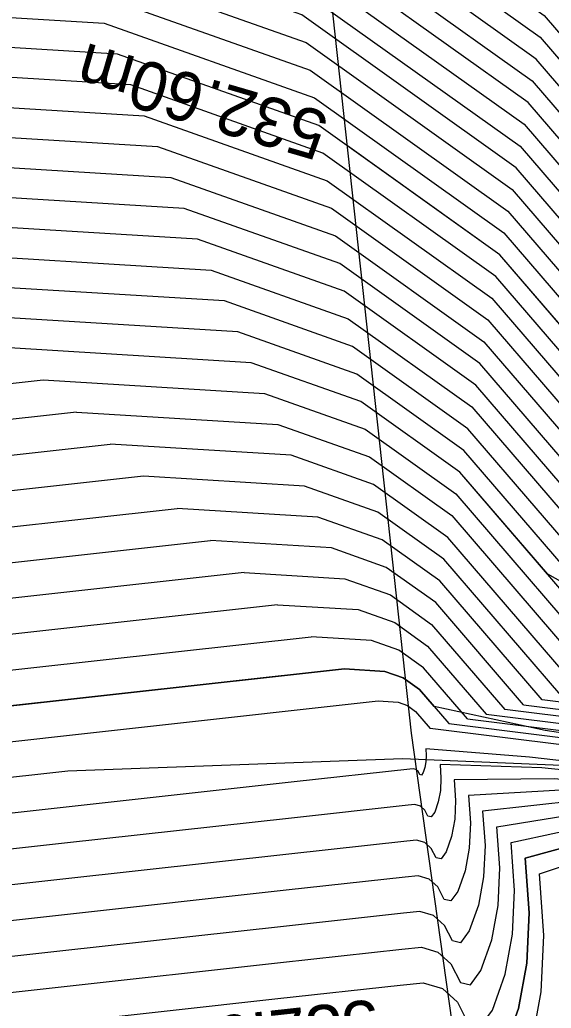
# Model space of a CAD drawing. Extents: x -866683 to -866410, y -1041951 to -1040252.
# Drawn here: x -866458.01 to -866454.76, y -1041924.15 to -1041918.11 of the extents above; entities that cross this region are included whole.
import ezdxf

# ---------------------------------------------------------------- set-up
doc = ezdxf.new("R2010")
doc.units = 0
for name, color, linetype in [('BODY', 7, 'Continuous'), ('BODY_2016', 7, 'Continuous'), ('BREAKLINE', 7, 'Continuous'), ('V-VEDL', 7, 'Continuous'), ('V_po_cm', 7, 'Continuous')]:
    doc.layers.add(name, color=color, linetype=linetype)

msp = doc.modelspace()

# ---------------------------------------------------------------- linework, layer by layer
at = {"layer": 'BREAKLINE'}
msp.add_lwpolyline([(-866451.679, -1041950.508), (-866455.618, -1041922.473), (-866456.719, -1041912.396), (-866455.207, -1041909.853), (-866453.752, -1041908.342), (-866450, -1041907.538), (-866447.7, -1041908.076), (-866445.165, -1041909.459), (-866437.422, -1041915.176), (-866426.565, -1041925.108), (-866438.22, -1041915.868), (-866445.312, -1041910.554), (-866447.7, -1041908.076)], dxfattribs=at)
at = {"layer": 'V-VEDL'}
for points in [[(-866462.1678, -1041916.1944), (-866458.2322, -1041916.4356), (-866456.4431, -1041917.0707), (-866454.8326, -1041918.2202), (-866453.4008, -1041919.8842), (-866452.2221, -1041921.0215), (-866451.2966, -1041921.6321), (-866449.952, -1041921.7999)], [(-866449.9128, -1041922.2361), (-866452.0438, -1041921.9702), (-866453.0823, -1041921.5002), (-866454.0937, -1041920.6932), (-866455.0781, -1041919.5492), (-866456.1853, -1041918.7589), (-866457.4153, -1041918.3223), (-866460.121, -1041918.1565)], [(-866449.8737, -1041922.6724), (-866452.791, -1041922.3082), (-866453.9424, -1041921.9789), (-866454.7865, -1041921.5022), (-866455.3235, -1041920.8782), (-866455.9274, -1041920.4471), (-866456.5983, -1041920.209), (-866458.0742, -1041920.1185)], [(-866462.3233, -1041923.0423), (-866462.0929, -1041922.841), (-866461.3549, -1041922.7006), (-866459.9943, -1041922.5205), (-866456.0274, -1041922.0806)], [(-866449.8345, -1041923.1086), (-866453.5381, -1041922.6463), (-866454.8025, -1041922.4576), (-866455.4794, -1041922.3112), (-866455.5689, -1041922.2072), (-866455.6696, -1041922.1354), (-866455.7814, -1041922.0957), (-866456.0274, -1041922.0806)], [(-866455.8588, -1041924.2509), (-866455.5364, -1041924.2176), (-866455.403, -1041924.2573), (-866455.2974, -1041924.3533), (-866455.2196, -1041924.5057), (-866455.1383, -1041924.5239), (-866455.0534, -1041924.4077), (-866454.9651, -1041924.1572), (-866454.9139, -1041923.8786), (-866454.9, -1041923.5718), (-866454.9234, -1041923.2368), (-866454.3666, -1041923.0849), (-866453.2296, -1041923.1162), (-866449.7953, -1041923.5448)]]:
    msp.add_lwpolyline(points, dxfattribs=at)
at = {"layer": 'V_po_cm'}
for points in [[(-866462.3725, -1041915.9982), (-866458.3139, -1041916.247), (-866456.4689, -1041916.9019), (-866454.8081, -1041918.0873), (-866451.8549, -1041921.5193)], [(-866452.083, -1041921.5771), (-866454.8572, -1041918.3531), (-866456.4173, -1041917.2395), (-866458.1505, -1041916.6243), (-866461.9631, -1041916.3906)], [(-866457.9843, -1041916.5236), (-866456.4431, -1041917.0707), (-866454.8326, -1041918.2202), (-866454.4544, -1041918.6598)], [(-866461.7584, -1041916.5869), (-866458.0689, -1041916.813), (-866456.3915, -1041917.4083), (-866454.8817, -1041918.486), (-866452.197, -1041921.606)], [(-866452.3111, -1041921.6349), (-866454.9063, -1041918.6189), (-866456.3658, -1041917.5772), (-866457.9872, -1041917.0016), (-866461.5538, -1041916.7831)], [(-866461.3491, -1041916.9793), (-866457.9055, -1041917.1903), (-866456.34, -1041917.746), (-866454.9308, -1041918.7518), (-866452.4251, -1041921.6638)], [(-866461.1444, -1041917.1755), (-866457.8238, -1041917.379), (-866456.3142, -1041917.9148), (-866454.9553, -1041918.8847), (-866452.5391, -1041921.6927)], [(-866452.6532, -1041921.7216), (-866454.9799, -1041919.0176), (-866456.2884, -1041918.0836), (-866457.7421, -1041917.5676), (-866460.9397, -1041917.3717)], [(-866460.735, -1041917.5679), (-866457.6604, -1041917.7563), (-866456.2626, -1041918.2524), (-866455.0044, -1041919.1505), (-866452.7672, -1041921.7505)], [(-866460.5304, -1041917.7641), (-866457.5787, -1041917.945), (-866456.2368, -1041918.4213), (-866455.029, -1041919.2834), (-866452.8812, -1041921.7794)], [(-866460.3257, -1041917.9603), (-866457.497, -1041918.1336), (-866456.211, -1041918.5901), (-866455.0535, -1041919.4163), (-866452.9953, -1041921.8083)], [(-866453.2233, -1041921.8661), (-866455.1026, -1041919.6821), (-866456.1595, -1041918.9277), (-866457.3336, -1041918.511), (-866459.9163, -1041918.3527)], [(-866459.7116, -1041918.5489), (-866457.2519, -1041918.6996), (-866456.1337, -1041919.0966), (-866455.1271, -1041919.815), (-866453.3373, -1041921.895)], [(-866459.5069, -1041918.7451), (-866457.1702, -1041918.8883), (-866456.1079, -1041919.2654), (-866455.1517, -1041919.9479), (-866453.4514, -1041921.9239)], [(-866453.1093, -1041921.8372), (-866455.0781, -1041919.5492), (-866456.0239, -1041918.8741)], [(-866459.3023, -1041918.9413), (-866457.0885, -1041919.077), (-866456.0821, -1041919.4342), (-866455.1762, -1041920.0808), (-866453.5654, -1041921.9528)], [(-866453.6794, -1041921.9817), (-866455.2008, -1041920.2137), (-866456.0563, -1041919.603), (-866457.0068, -1041919.2656), (-866459.0976, -1041919.1375)], [(-866453.7935, -1041922.0106), (-866455.2253, -1041920.3466), (-866456.0306, -1041919.7718), (-866456.9251, -1041919.4543), (-866458.8929, -1041919.3337)], [(-866458.6882, -1041919.5299), (-866456.8434, -1041919.643), (-866456.0048, -1041919.9407), (-866455.2499, -1041920.4795), (-866453.9075, -1041922.0395)], [(-866454.0215, -1041922.0684), (-866455.2744, -1041920.6124), (-866455.979, -1041920.1095), (-866456.7617, -1041919.8317), (-866458.4835, -1041919.7261)], [(-866454.1356, -1041922.0973), (-866455.2989, -1041920.7453), (-866455.9532, -1041920.2783), (-866456.68, -1041920.0203), (-866458.2789, -1041919.9223)], [(-866454.2496, -1041922.1262), (-866455.3235, -1041920.8782), (-866455.9274, -1041920.4471), (-866456.5983, -1041920.209), (-866458.0742, -1041920.1185)], [(-866462.5037, -1041921.0226), (-866462.3342, -1041920.8745), (-866461.791, -1041920.7711), (-866460.7894, -1041920.6385), (-866457.8695, -1041920.3147)], [(-866457.8695, -1041920.3147), (-866456.5166, -1041920.3977), (-866455.9016, -1041920.616), (-866455.348, -1041921.0111), (-866454.3636, -1041922.1551)], [(-866457.6648, -1041920.511), (-866460.7011, -1041920.8476), (-866461.7425, -1041920.9855), (-866462.3073, -1041921.093), (-866462.4837, -1041921.247)], [(-866457.6648, -1041920.511), (-866456.435, -1041920.5863), (-866455.8758, -1041920.7848), (-866455.3726, -1041921.144), (-866454.4777, -1041922.184)], [(-866462.4636, -1041921.4714), (-866462.2805, -1041921.3115), (-866461.6941, -1041921.1999), (-866460.6127, -1041921.0567), (-866457.4601, -1041920.7072)], [(-866454.5917, -1041922.2129), (-866455.3971, -1041921.2769), (-866455.8501, -1041920.9536), (-866456.3533, -1041920.775), (-866457.4601, -1041920.7072)], [(-866457.2555, -1041920.9034), (-866460.5244, -1041921.2658), (-866461.6456, -1041921.4143), (-866462.2537, -1041921.53), (-866462.4436, -1041921.6958)], [(-866454.7057, -1041922.2418), (-866455.4217, -1041921.4098), (-866455.8243, -1041921.1224), (-866456.2716, -1041920.9637), (-866457.2555, -1041920.9034)], [(-866462.4235, -1041921.9203), (-866462.2269, -1041921.7485), (-866461.5972, -1041921.6287), (-866460.436, -1041921.475), (-866457.0508, -1041921.0996)], [(-866454.8198, -1041922.2707), (-866455.4462, -1041921.5427), (-866455.7985, -1041921.2912), (-866456.1899, -1041921.1523), (-866457.0508, -1041921.0996)], [(-866462.4035, -1041922.1447), (-866462.2001, -1041921.967), (-866461.5487, -1041921.8431), (-866460.3477, -1041921.6841), (-866456.8461, -1041921.2958)], [(-866454.9338, -1041922.2996), (-866455.4707, -1041921.6756), (-866455.7727, -1041921.4601), (-866456.1082, -1041921.341), (-866456.8461, -1041921.2958)], [(-866456.6414, -1041921.492), (-866460.2593, -1041921.8932), (-866461.5003, -1041922.0575), (-866462.1733, -1041922.1855), (-866462.3834, -1041922.3691)], [(-866456.6414, -1041921.492), (-866456.0265, -1041921.5297), (-866455.7469, -1041921.6289), (-866455.4953, -1041921.8085), (-866455.0478, -1041922.3285)], [(-866456.4367, -1041921.6882), (-866460.171, -1041922.1023), (-866461.4518, -1041922.2719), (-866462.1465, -1041922.404), (-866462.3634, -1041922.5935)], [(-866456.4367, -1041921.6882), (-866455.9448, -1041921.7183), (-866455.7211, -1041921.7977), (-866455.5198, -1041921.9414), (-866455.1619, -1041922.3574)], [(-866462.3433, -1041922.8179), (-866462.1197, -1041922.6225), (-866461.4034, -1041922.4863), (-866460.0826, -1041922.3114), (-866456.232, -1041921.8844)], [(-866455.2759, -1041922.3863), (-866455.5444, -1041922.0743), (-866455.6954, -1041921.9665), (-866455.8631, -1041921.907), (-866456.232, -1041921.8844)], [(-866456.0274, -1041922.0806), (-866458.2347, -1041922.3254)], [(-866456.0274, -1041922.0806), (-866455.7814, -1041922.0957), (-866455.6696, -1041922.1354), (-866455.5689, -1041922.2072), (-866455.3899, -1041922.4152)], [(-866462.3032, -1041923.2667), (-866462.0661, -1041923.0595), (-866461.3065, -1041922.915), (-866459.9059, -1041922.7296), (-866455.8227, -1041922.2768)], [(-866455.8227, -1041922.2768), (-866455.6997, -1041922.2843), (-866455.6438, -1041922.3042), (-866455.5935, -1041922.3401), (-866455.504, -1041922.4441)], [(-866447.6566, -1041942.39), (-866443.865, -1041936.08), (-866442.6338, -1041933.8151), (-866442.0673, -1041932.4403), (-866442.1655, -1041931.9556), (-866442.1705, -1041931.1056), (-866442.0824, -1041929.8904), (-866441.9012, -1041928.3099), (-866442.5034, -1041926.7821), (-866443.8893, -1041925.307), (-866446.0587, -1041923.8847), (-866447.6856, -1041922.984), (-866448.77, -1041922.6051), (-866449.3121, -1041922.7478), (-866450.2251, -1041922.774), (-866451.5093, -1041922.6839), (-866454.8198, -1041922.2707)], [(-866447.9552, -1041942.6485), (-866444.0987, -1041936.2305), (-866442.8465, -1041933.9269), (-866442.2703, -1041932.5286), (-866442.3702, -1041932.0356), (-866442.3753, -1041931.1711), (-866442.2857, -1041929.935), (-866442.1013, -1041928.3275), (-866442.6833, -1041926.7936), (-866444.0317, -1041925.3334), (-866446.1464, -1041923.9469), (-866447.7324, -1041923.0689), (-866448.7895, -1041922.6995), (-866449.3179, -1041922.8386), (-866450.2481, -1041922.8592), (-866451.5801, -1041922.7613), (-866455.0478, -1041922.3285)], [(-866454.9338, -1041922.2996), (-866451.5447, -1041922.7226), (-866450.2366, -1041922.8166), (-866449.315, -1041922.7932), (-866448.7798, -1041922.6523), (-866447.709, -1041923.0265), (-866446.1025, -1041923.9158), (-866443.9605, -1041925.3202), (-866442.5934, -1041926.7878), (-866442.0012, -1041928.3187), (-866442.184, -1041929.9127), (-866442.2729, -1041931.1384), (-866442.2678, -1041931.9956), (-866442.1688, -1041932.4844), (-866442.7402, -1041933.871), (-866443.9818, -1041936.1553), (-866447.8059, -1041942.5192)], [(-866455.2759, -1041922.3863), (-866451.6509, -1041922.8387), (-866450.271, -1041922.9444), (-866449.3237, -1041922.9294), (-866448.809, -1041922.7939), (-866447.7791, -1041923.1538), (-866446.2342, -1041924.0091), (-866444.1741, -1041925.3598), (-866442.8632, -1041926.8051), (-866442.3015, -1041928.3451), (-866442.4889, -1041929.9797), (-866442.5801, -1041931.2365), (-866442.5749, -1041932.1155), (-866442.4733, -1041932.6168), (-866443.0592, -1041934.0386), (-866444.3325, -1041936.381), (-866448.2538, -1041942.907)], [(-866455.1619, -1041922.3574), (-866451.6155, -1041922.8), (-866450.2595, -1041922.9018), (-866449.3208, -1041922.884), (-866448.7992, -1041922.7467), (-866447.7558, -1041923.1114), (-866446.1903, -1041923.978), (-866444.1029, -1041925.3466), (-866442.7733, -1041926.7993), (-866442.2014, -1041928.3363), (-866442.3873, -1041929.9573), (-866442.4777, -1041931.2038), (-866442.4725, -1041932.0756), (-866442.3718, -1041932.5727), (-866442.9528, -1041933.9828), (-866444.2156, -1041936.3058), (-866448.1045, -1041942.7777)], [(-866448.5524, -1041943.1654), (-866444.5662, -1041936.5316), (-866443.2719, -1041934.1504), (-866442.6763, -1041932.7051), (-866442.7795, -1041932.1955), (-866442.7848, -1041931.3019), (-866442.6922, -1041930.0243), (-866442.5016, -1041928.3626), (-866443.0431, -1041926.8166), (-866444.3165, -1041925.3861), (-866446.322, -1041924.0713), (-866447.8259, -1041923.2387), (-866448.8285, -1041922.8884), (-866449.3295, -1041923.0203), (-866450.2939, -1041923.0295), (-866451.7217, -1041922.9162), (-866455.504, -1041922.4441)], [(-866455.3899, -1041922.4152), (-866453.1181, -1041922.6987)], [(-866448.8479, -1041922.9828), (-866449.3353, -1041923.1111), (-866450.2949, -1041923.1175), (-866451.7265, -1041923.0018), (-866453.6303, -1041922.7642), (-866454.8985, -1041922.6198), (-866455.5312, -1041922.5685), (-866455.5283, -1041922.6104), (-866455.53, -1041922.6487), (-866455.5364, -1041922.6835), (-866455.5474, -1041922.7148), (-866455.558, -1041922.7294), (-866455.5682, -1041922.7271), (-866455.5779, -1041922.708), (-866455.5911, -1041922.696), (-866455.6078, -1041922.6911), (-866455.6279, -1041922.6932), (-866456.3346, -1041922.7714), (-866457.7278, -1041922.9259), (-866459.8075, -1041923.1565), (-866461.2357, -1041923.3467), (-866462.0125, -1041923.4966), (-866462.2631, -1041923.7155)], [(-866448.7017, -1041943.2947), (-866444.6831, -1041936.6068), (-866443.3782, -1041934.2063), (-866442.7778, -1041932.7492), (-866442.8819, -1041932.2355), (-866442.8872, -1041931.3346), (-866442.7938, -1041930.0466), (-866442.6017, -1041928.3714), (-866443.133, -1041926.8223), (-866444.3877, -1041925.3993), (-866446.3658, -1041924.1024), (-866447.8493, -1041923.2811), (-866448.8382, -1041922.9356), (-866449.3324, -1041923.0657), (-866450.3054, -1041923.0721), (-866451.7571, -1041922.9549), (-866453.6875, -1041922.7139), (-866455.6744, -1041922.6309), (-866457.7178, -1041922.7058), (-866459.8175, -1041922.9387), (-866461.2581, -1041923.1294), (-866462.0393, -1041923.2781), (-866462.2832, -1041923.4911)], [(-866448.8577, -1041923.03), (-866449.3382, -1041923.1565), (-866450.2843, -1041923.1628), (-866451.6959, -1041923.0488), (-866453.5731, -1041922.8145), (-866454.8225, -1041922.6862), (-866455.4443, -1041922.664), (-866455.4385, -1041922.7477), (-866455.442, -1041922.8244), (-866455.4548, -1041922.8941), (-866455.4769, -1041922.9567), (-866455.4981, -1041922.9857), (-866455.5184, -1041922.9812), (-866455.5379, -1041922.9431), (-866455.5643, -1041922.9191), (-866455.5976, -1041922.9091), (-866455.6379, -1041922.9133), (-866456.3513, -1041922.9922), (-866457.7378, -1041923.1459), (-866459.7974, -1041923.3743), (-866461.2133, -1041923.564), (-866461.9857, -1041923.7151), (-866462.2431, -1041923.9399)], [(-866448.8674, -1041923.0772), (-866449.3411, -1041923.2019), (-866450.2738, -1041923.2081), (-866451.6653, -1041923.0957), (-866453.5158, -1041922.8648), (-866454.7465, -1041922.7527), (-866455.3575, -1041922.7594), (-866455.3488, -1041922.8851), (-866455.354, -1041923.0001), (-866455.3731, -1041923.1046), (-866455.4063, -1041923.1985), (-866455.4381, -1041923.2421), (-866455.4686, -1041923.2353), (-866455.4978, -1041923.1781), (-866455.5374, -1041923.1421), (-866455.5874, -1041923.1272), (-866455.6478, -1041923.1335), (-866456.368, -1041923.213), (-866457.7478, -1041923.3659), (-866459.7873, -1041923.592), (-866461.191, -1041923.7813), (-866461.9589, -1041923.9336), (-866462.223, -1041924.1643)], [(-866448.8771, -1041923.1244), (-866449.344, -1041923.2474), (-866450.2633, -1041923.2534), (-866451.6348, -1041923.1427), (-866453.4586, -1041922.915), (-866454.6705, -1041922.8191), (-866455.2707, -1041922.8549), (-866455.259, -1041923.0224), (-866455.266, -1041923.1758), (-866455.2915, -1041923.3151), (-866455.3357, -1041923.4404), (-866455.3782, -1041923.4984), (-866455.4188, -1041923.4894), (-866455.4577, -1041923.4132), (-866455.5105, -1041923.3651), (-866455.5772, -1041923.3453), (-866455.6578, -1041923.3536), (-866456.3847, -1041923.4338), (-866457.7578, -1041923.5859), (-866459.7772, -1041923.8098), (-866461.1686, -1041923.9985), (-866461.9321, -1041924.1521), (-866462.203, -1041924.3887)], [(-866448.8869, -1041923.1717), (-866449.347, -1041923.2928), (-866450.2527, -1041923.2988), (-866451.6042, -1041923.1896), (-866453.4013, -1041922.9653), (-866454.5945, -1041922.8856), (-866455.1839, -1041922.9504), (-866455.1693, -1041923.1598), (-866455.1779, -1041923.3515), (-866455.2099, -1041923.5257), (-866455.2652, -1041923.6822), (-866455.3182, -1041923.7548), (-866455.369, -1041923.7435), (-866455.4176, -1041923.6482), (-866455.4836, -1041923.5882), (-866455.567, -1041923.5634), (-866455.6677, -1041923.5738), (-866456.4013, -1041923.6546), (-866457.7678, -1041923.8059), (-866459.7671, -1041924.0276), (-866461.1462, -1041924.2158), (-866461.9052, -1041924.3706), (-866462.1829, -1041924.6131)], [(-866462.1629, -1041924.8375), (-866461.8784, -1041924.5891), (-866461.1239, -1041924.4331), (-866459.757, -1041924.2454), (-866457.7778, -1041924.0259), (-866456.418, -1041923.8754), (-866455.6777, -1041923.7939), (-866455.5568, -1041923.7814), (-866455.4568, -1041923.8112), (-866455.3776, -1041923.8832), (-866455.3192, -1041923.9975), (-866455.2582, -1041924.0111), (-866455.1946, -1041923.924), (-866455.1283, -1041923.7362), (-866455.0899, -1041923.5272), (-866455.0795, -1041923.2971), (-866455.097, -1041923.0459), (-866454.5186, -1041922.952), (-866453.3441, -1041923.0156), (-866451.5736, -1041923.2366), (-866450.2422, -1041923.3441), (-866449.3499, -1041923.3382), (-866448.8966, -1041923.2189)], [(-866462.1428, -1041925.062), (-866461.8516, -1041924.8076), (-866461.1015, -1041924.6504), (-866459.7469, -1041924.4632), (-866457.7878, -1041924.2459), (-866456.4347, -1041924.0962), (-866455.6876, -1041924.0141), (-866455.5466, -1041923.9995), (-866455.4299, -1041924.0342), (-866455.3375, -1041924.1183), (-866455.2694, -1041924.2516), (-866455.1983, -1041924.2675), (-866455.124, -1041924.1659), (-866455.0467, -1041923.9467), (-866455.0019, -1041923.7029), (-866454.9898, -1041923.4345), (-866455.0102, -1041923.1413), (-866454.4426, -1041923.0185), (-866453.2868, -1041923.0659), (-866451.543, -1041923.2835), (-866450.2317, -1041923.3894), (-866449.3528, -1041923.3836), (-866448.9063, -1041923.2661)], [(-866452.7723, -1041923.1732), (-866453.2296, -1041923.1162), (-866454.3666, -1041923.0849), (-866454.9234, -1041923.2368), (-866454.9, -1041923.5718), (-866454.9139, -1041923.8786), (-866454.9651, -1041924.1572), (-866455.0534, -1041924.4077), (-866455.1383, -1041924.5239), (-866455.2196, -1041924.5057), (-866455.2974, -1041924.3533), (-866455.403, -1041924.2573), (-866455.5364, -1041924.2176), (-866455.688, -1041924.2333)], [(-866462.1027, -1041925.5108), (-866461.798, -1041925.2446), (-866461.0568, -1041925.085), (-866459.7267, -1041924.8987), (-866457.8078, -1041924.6859), (-866456.4681, -1041924.5378), (-866455.7075, -1041924.4544), (-866455.5262, -1041924.4356), (-866455.3761, -1041924.4803), (-866455.2574, -1041924.5883), (-866455.1698, -1041924.7598), (-866455.0783, -1041924.7802), (-866454.9829, -1041924.6495), (-866454.8834, -1041924.3678), (-866454.8259, -1041924.0543), (-866454.8103, -1041923.7092), (-866454.8365, -1041923.3323), (-866454.2906, -1041923.1514), (-866453.1723, -1041923.1664), (-866451.4819, -1041923.3774), (-866450.2106, -1041923.4801), (-866449.3586, -1041923.4745), (-866448.9258, -1041923.3605)]]:
    msp.add_lwpolyline(points, dxfattribs=at)

# ---------------------------------------------------------------- texts
at = {"layer": 'BODY'}
msp.add_text('+', height=0.001, rotation=360, dxfattribs=at).set_placement((-866455.618, -1041922.473))
at = {"layer": 'BODY_2016'}
msp.add_text('+', height=0.001, rotation=360, dxfattribs=at).set_placement((-866455.618, -1041922.473))
at = {"layer": 'V_po_cm'}
for s, rotation, p in [('532.60m', 163.7182, (-866456.1094, -1041918.6889)), ('532.90m', 186.2934, (-866455.8337, -1041924.0984))]:
    msp.add_text(s, height=0.3, rotation=rotation, dxfattribs=at).set_placement(p)

doc.saveas('drawing.dxf')
